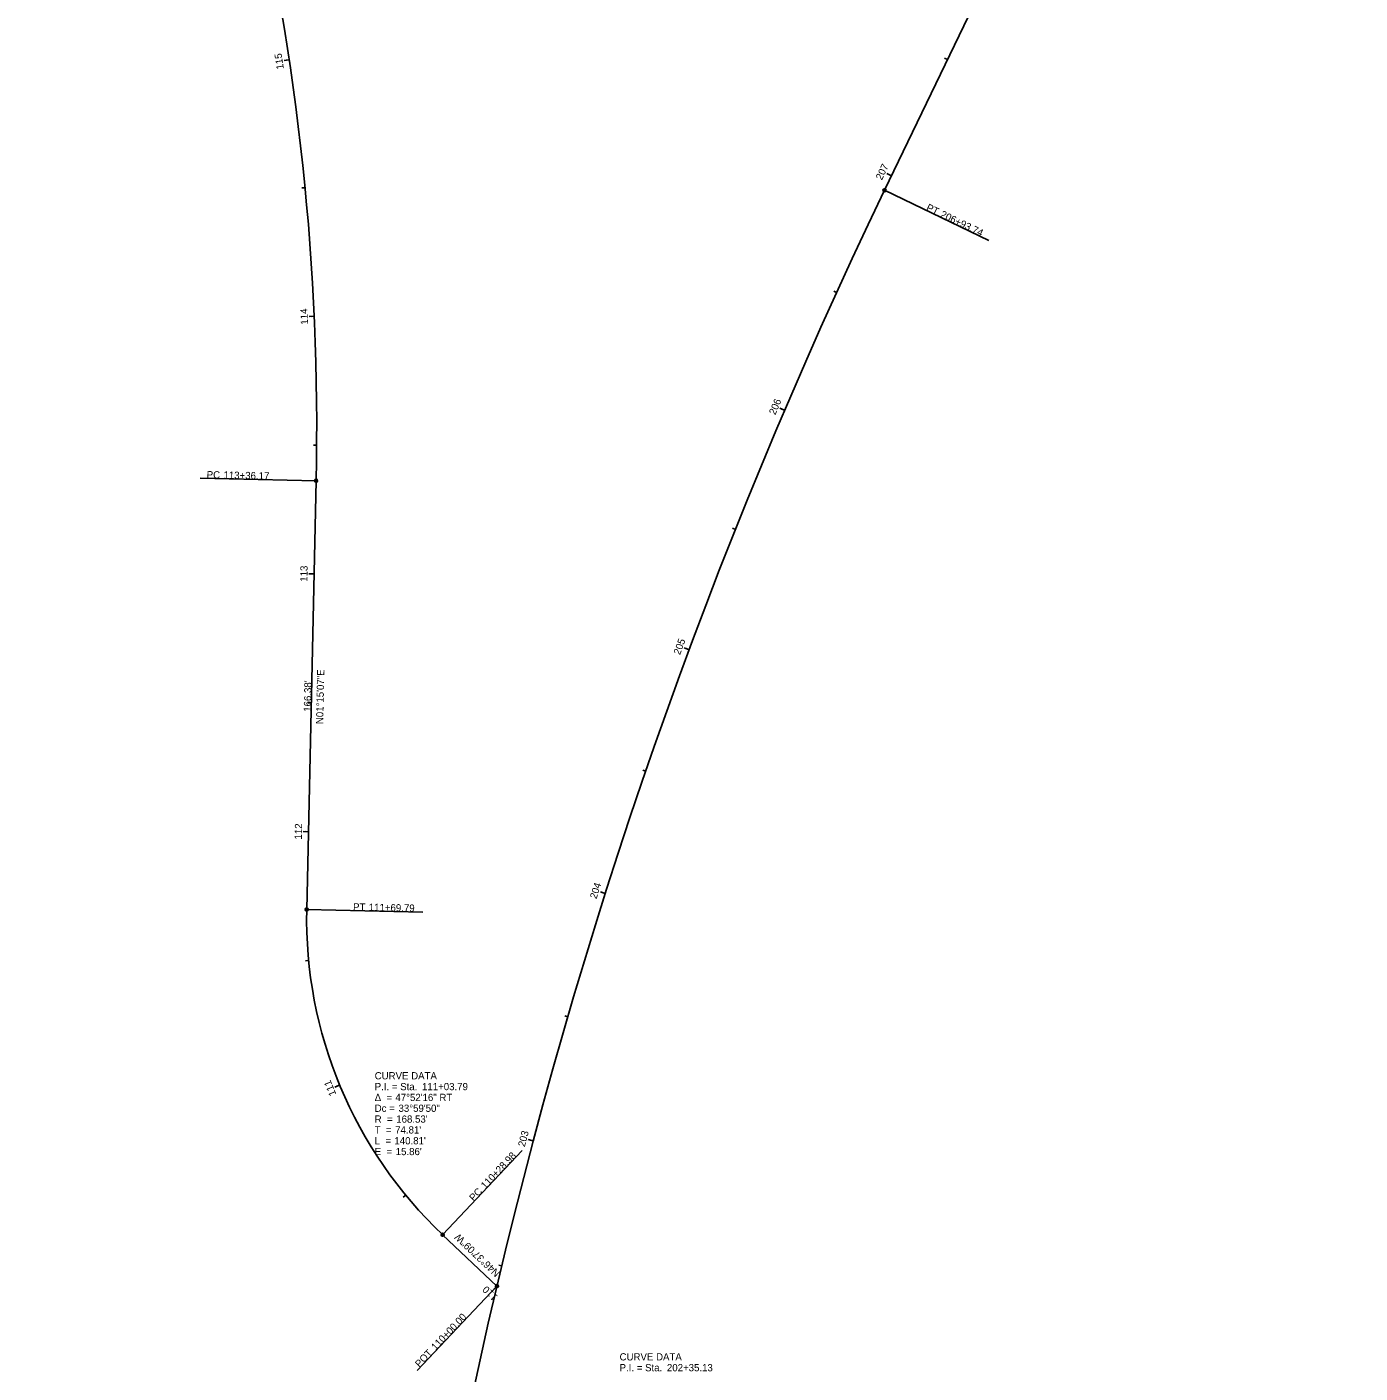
# Model space of a CAD drawing. Extents: x 1564507 to 1565178, y 635740 to 637470.
# Drawn here: x 1564660 to 1565177, y 636440 to 636962 of the extents above; entities that cross this region are included whole.
import ezdxf

# ---------------------------------------------------------------- set-up
doc = ezdxf.new("R2010")
doc.units = 0
for name, color, linetype in [('_CIVIL_CONSTRUCTION', 7, 'Continuous'), ('PM_P_CL_Double_Solid', 7, 'Continuous'), ('PM_P_Edge_Line', 7, 'Continuous'), ('PV_P_EOP', 7, 'Continuous'), ('PV_P_Shoulder', 7, 'Continuous'), ('RD_P_Wall', 7, 'Continuous'), ('RW_P_Const_Limits', 7, 'Continuous'), ('SC_Scratch1', 7, 'Continuous'), ('SC_Scratch2', 7, 'Continuous'), ('SC_Shading1', 7, 'Continuous'), ('SC_Shading3', 7, 'Continuous'), ('TR_Turning_Path2', 7, 'Continuous'), ('TR_Turning_Path5', 7, 'Continuous'), ('TR_Turning_Path6', 7, 'Continuous'), ('VG_P_Landscape_Limits', 7, 'Continuous')]:
    doc.layers.add(name, color=color, linetype=linetype)

msp = doc.modelspace()

# ---------------------------------------------------------------- linework, layer by layer
at = {"layer": '_CIVIL_CONSTRUCTION'}
for p, q in [((1564761.81, 636949.56), (1564760.62, 636949.38)), ((1564916.98, 636720.72), (1564915.86, 636721.14)), ((1564842.42, 636473.84), (1564841.05, 636472.39))]:
    msp.add_line(p, q, dxfattribs=at)
at = {"layer": 'PM_P_CL_Double_Solid'}
for p, q in [((1564761.81, 636949.56), (1564759.83, 636949.26)), ((1565017.2, 636949.63), (1565016.12, 636950.15)), ((1564995.5, 636904.58), (1564993.7, 636905.45)), ((1564767.97, 636899.94), (1564766.77, 636899.83)), ((1564974.22, 636859.34), (1564973.13, 636859.84)), ((1564771.52, 636850.07), (1564769.52, 636849.98)), ((1564954.03, 636813.6), (1564952.19, 636814.38)), ((1564772.46, 636800.09), (1564771.26, 636800.1)), ((1564934.95, 636767.38), (1564933.83, 636767.83)), ((1564771.47, 636750.1), (1564769.47, 636750.14)), ((1564916.98, 636720.72), (1564915.11, 636721.42)), ((1564770.38, 636700.11), (1564769.18, 636700.14)), ((1564900.15, 636673.64), (1564899.01, 636674.04)), ((1564769.29, 636650.12), (1564767.29, 636650.17)), ((1564884.45, 636626.17), (1564882.55, 636626.78)), ((1564769.35, 636600.16), (1564768.16, 636600.04)), ((1564869.9, 636578.34), (1564868.75, 636578.67)), ((1564781.38, 636551.81), (1564779.54, 636551.05)), ((1564856.51, 636530.17), (1564854.58, 636530.68)), ((1564807.02, 636509.1), (1564806.1, 636508.34)), ((1564844.29, 636481.69), (1564843.12, 636481.96)), ((1564842.42, 636473.84), (1564841.05, 636472.39))]:
    msp.add_line(p, q, dxfattribs=at)
at = {"layer": 'PV_P_EOP'}
for p, q in [((1564992.79, 636898.95), (1565033.33, 636879.42)), ((1564772.26, 636786.26), (1564727.27, 636787.25)), ((1564768.63, 636619.92), (1564813.61, 636618.94)), ((1564821.36, 636493.75), (1564852.27, 636526.45))]:
    msp.add_line(p, q, dxfattribs=at)
for centre in [(1564992.79, 636898.95), (1564772.26, 636786.26), (1564768.63, 636619.92), (1564821.36, 636493.75)]:
    msp.add_circle(centre, 0.6, dxfattribs=at)
at = {"layer": 'PV_P_Shoulder'}
for p, q in [((1564992.79, 636898.95), (1565033.33, 636879.42)), ((1564772.26, 636786.26), (1564727.27, 636787.25)), ((1564768.63, 636619.92), (1564813.61, 636618.94)), ((1564821.36, 636493.75), (1564852.27, 636526.45)), ((1564842.42, 636473.84), (1564811.52, 636441.14))]:
    msp.add_line(p, q, dxfattribs=at)
for centre in [(1564992.79, 636898.95), (1564772.26, 636786.26), (1564768.63, 636619.92), (1564821.36, 636493.75), (1564842.42, 636473.84)]:
    msp.add_circle(centre, 0.6, dxfattribs=at)
at = {"layer": 'SC_Scratch2'}
for p, q in [((1564761.81, 636949.56), (1564759.83, 636949.26)), ((1564995.5, 636904.58), (1564994.42, 636905.1)), ((1564771.52, 636850.07), (1564770.32, 636850.02)), ((1564954.03, 636813.6), (1564952.93, 636814.07)), ((1564771.47, 636750.1), (1564770.27, 636750.13)), ((1564916.98, 636720.72), (1564915.11, 636721.42)), ((1564769.29, 636650.12), (1564768.09, 636650.15)), ((1564884.45, 636626.17), (1564883.31, 636626.54)), ((1564781.38, 636551.81), (1564780.28, 636551.35)), ((1564856.51, 636530.17), (1564855.35, 636530.47)), ((1564842.42, 636473.84), (1564841.05, 636472.39))]:
    msp.add_line(p, q, dxfattribs=at)
at = {"layer": 'SC_Shading3'}
for p, q in [((1564992.79, 636898.95), (1565033.33, 636879.42)), ((1564772.26, 636786.26), (1564727.27, 636787.25)), ((1564768.63, 636619.92), (1564813.61, 636618.94)), ((1564821.36, 636493.75), (1564852.27, 636526.45)), ((1564842.42, 636473.84), (1564811.52, 636441.14))]:
    msp.add_line(p, q, dxfattribs=at)
for centre in [(1564992.79, 636898.95), (1564772.26, 636786.26), (1564768.63, 636619.92), (1564821.36, 636493.75), (1564842.42, 636473.84)]:
    msp.add_circle(centre, 0.6, dxfattribs=at)
at = {"layer": 'TR_Turning_Path2'}
for p, q in [((1564992.79, 636898.95), (1565177.32, 637282.11)), ((1564992.79, 636898.95), (1565177.32, 637282.11)), ((1564768.63, 636619.92), (1564772.26, 636786.26)), ((1564768.63, 636619.92), (1564772.26, 636786.26)), ((1564842.42, 636473.84), (1564821.36, 636493.75)), ((1564842.42, 636473.84), (1564821.36, 636493.75))]:
    msp.add_line(p, q, dxfattribs=at)
for centre, radius, start, end in [((1563817.53, 636807.13), 954.96, 358.74802, 28.08321), ((1563817.53, 636807.13), 954.96, 358.74802, 28.08321), ((1566862.66, 635998.41), 2075.42, 154.28444, 180.04915), ((1566862.66, 635998.41), 2075.42, 154.28444, 180.04915), ((1564937.12, 636616.24), 168.53, 178.748, 226.6192), ((1564937.12, 636616.24), 168.53, 178.748, 226.6192)]:
    msp.add_arc(centre, radius, start, end, dxfattribs=at)

# ---------------------------------------------------------------- texts
at = {"layer": '_CIVIL_CONSTRUCTION'}
msp.add_text('110', height=2.8, rotation=136.6192, dxfattribs=at).set_placement((1564842.95, 636469.84))
at = {"layer": 'PM_P_CL_Double_Solid'}
for s, rotation, p in [('115', 98.5774, (1564759.76, 636946.06)), ('207', 64.2844, (1564991.76, 636902.68)), ('114', 92.5776, (1564769.16, 636846.87)), ('206', 66.8724, (1564950.4, 636811.58)), ('113', 88.748, (1564768.86, 636747.04)), ('205', 69.633, (1564913.45, 636718.52)), ('112', 88.748, (1564766.72, 636647.05)), ('204', 72.3937, (1564881.05, 636623.86)), ('111', 112.474, (1564780.15, 636548.25)), ('203', 75.1544, (1564853.21, 636527.66)), ('110', 136.6192, (1564842.95, 636469.84))]:
    msp.add_text(s, height=2.8, rotation=rotation, dxfattribs=at).set_placement(p)
at = {"layer": 'PM_P_Edge_Line'}
for s, rotation, p in [('N01°15\'07"E', 88.748, (1564775, 636691.81)), ('N46°37\'09"W', 136.6192, (1564843.81, 636479.13))]:
    msp.add_text(s, height=2.8, rotation=rotation, dxfattribs=at).set_placement(p)
at = {"layer": 'PV_P_EOP'}
for s, rotation, p in [('PT', 334.2844, (1565008.74, 636891.31)), ('206+93.74', 334.2844, (1565014.22, 636888.67)), ('PC', 358.748, (1564729.78, 636787.24)), ('113+36.17', 358.748, (1564736.3, 636787.1)), ('PT', 358.748, (1564786.58, 636619.57)), ('111+69.79', 358.748, (1564792.67, 636619.44)), ('110+28.98', 46.6192, (1564837.88, 636511.29)), ('PC', 46.6192, (1564833.4, 636506.55))]:
    msp.add_text(s, height=2.8, rotation=rotation, dxfattribs=at).set_placement(p)
at = {"layer": 'PV_P_Shoulder'}
for s, rotation, p in [('PT', 334.2844, (1565008.74, 636891.31)), ('206+93.74', 334.2844, (1565014.22, 636888.67)), ('PC', 358.748, (1564729.78, 636787.24)), ('113+36.17', 358.748, (1564736.3, 636787.1)), ('PT', 358.748, (1564786.58, 636619.57)), ('111+69.79', 358.748, (1564792.67, 636619.44)), ('110+28.98', 46.6192, (1564837.88, 636511.29)), ('PC', 46.6192, (1564833.4, 636506.55)), ('110+00.00', 46.6192, (1564818.62, 636448.72)), ('POT', 46.6192, (1564812.35, 636442.09))]:
    msp.add_text(s, height=2.8, rotation=rotation, dxfattribs=at).set_placement(p)
at = {"layer": 'RD_P_Wall'}
msp.add_text("166.38'", height=2.8, rotation=88.748, dxfattribs=at).set_placement((1564770.25, 636696.61))
at = {"layer": 'RW_P_Const_Limits'}
msp.add_text("166.38'", height=2.8, rotation=88.748, dxfattribs=at).set_placement((1564770.25, 636696.61))
at = {"layer": 'SC_Scratch1'}
msp.add_text("166.38'", height=2.8, rotation=88.748, dxfattribs=at).set_placement((1564770.25, 636696.61))
at = {"layer": 'SC_Scratch2'}
for s, rotation, p in [('115', 98.5774, (1564759.76, 636946.06)), ('205', 69.633, (1564913.45, 636718.52)), ('110', 136.6192, (1564842.95, 636469.84))]:
    msp.add_text(s, height=2.8, rotation=rotation, dxfattribs=at).set_placement(p)
at = {"layer": 'SC_Shading1'}
for s, rotation, p in [('N01°15\'07"E', 88.748, (1564775, 636691.81)), ('N46°37\'09"W', 136.6192, (1564843.81, 636479.13))]:
    msp.add_text(s, height=2.8, rotation=rotation, dxfattribs=at).set_placement(p)
at = {"layer": 'SC_Shading3'}
for s, rotation, p in [('PT', 334.2844, (1565008.74, 636891.31)), ('206+93.74', 334.2844, (1565014.22, 636888.67)), ('PC', 358.748, (1564729.78, 636787.24)), ('113+36.17', 358.748, (1564736.3, 636787.1)), ('PT', 358.748, (1564786.58, 636619.57)), ('111+69.79', 358.748, (1564792.67, 636619.44)), ('110+28.98', 46.6192, (1564837.88, 636511.29)), ('PC', 46.6192, (1564833.4, 636506.55)), ('110+00.00', 46.6192, (1564818.62, 636448.72)), ('POT', 46.6192, (1564812.35, 636442.09))]:
    msp.add_text(s, height=2.8, rotation=rotation, dxfattribs=at).set_placement(p)
at = {"layer": 'TR_Turning_Path5'}
for s, rotation, p in [('N01°15\'07"E', 88.748, (1564775, 636691.81)), ('N46°37\'09"W', 136.6192, (1564843.81, 636479.13))]:
    msp.add_text(s, height=2.8, rotation=rotation, dxfattribs=at).set_placement(p)
at = {"layer": 'TR_Turning_Path6'}
for s, p in [('CURVE DATA', (1564794.99, 636554.03)), ('P.I. = Sta. ', (1564794.99, 636549.83)), ('111+03.79', (1564813.36, 636549.83)), ('Δ  = ', (1564794.99, 636545.63)), ('47°52\'16" RT', (1564803.02, 636545.63)), ('Dc = ', (1564794.99, 636541.43)), ('33°59\'50"', (1564804.23, 636541.43)), ('T  = ', (1564794.99, 636533.03)), ('R  = ', (1564794.99, 636537.23)), ("74.81'", (1564802.93, 636533.03)), ("168.53'", (1564803.36, 636537.23)), ('L  = ', (1564794.99, 636528.83)), ("140.81'", (1564802.64, 636528.83)), ('E  = ', (1564794.99, 636524.63)), ("15.86'", (1564803.15, 636524.63)), ('CURVE DATA', (1564890.01, 636444.99)), ('P.I. = Sta. ', (1564890.01, 636440.79)), ('202+35.13', (1564908.38, 636440.79))]:
    msp.add_text(s, height=2.8, dxfattribs=at).set_placement(p)
at = {"layer": 'VG_P_Landscape_Limits'}
for s, p in [('CURVE DATA', (1564794.99, 636554.03)), ('P.I. = Sta. ', (1564794.99, 636549.83)), ('111+03.79', (1564813.36, 636549.83)), ('Δ  = ', (1564794.99, 636545.63)), ('47°52\'16" RT', (1564803.02, 636545.63)), ('Dc = ', (1564794.99, 636541.43)), ('33°59\'50"', (1564804.23, 636541.43)), ('T  = ', (1564794.99, 636533.03)), ('R  = ', (1564794.99, 636537.23)), ("74.81'", (1564802.93, 636533.03)), ("168.53'", (1564803.36, 636537.23)), ('L  = ', (1564794.99, 636528.83)), ("140.81'", (1564802.64, 636528.83)), ('E  = ', (1564794.99, 636524.63)), ("15.86'", (1564803.15, 636524.63)), ('CURVE DATA', (1564890.01, 636444.99)), ('P.I. = Sta. ', (1564890.01, 636440.79)), ('202+35.13', (1564908.38, 636440.79))]:
    msp.add_text(s, height=2.8, dxfattribs=at).set_placement(p)

doc.saveas('drawing.dxf')
